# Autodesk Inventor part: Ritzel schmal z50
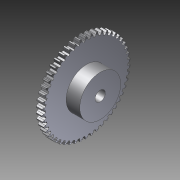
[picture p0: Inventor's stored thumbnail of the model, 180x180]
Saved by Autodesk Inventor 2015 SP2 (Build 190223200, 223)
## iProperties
Created: 2015-08
Part Number: Ritzel schmal z50
Material: Messing, weicher Gelbton
Document SubType Name: Modeling
Designer: ryll
Mass: 11.7013 g
Surface Area: 14.4914 cm^2
Volume: 1.3815 cm^3
Density: 8.47 g/cm^3
Appearance: Messing - satiniert
Title: c:/PPEXPORT/antriebselemente_und_normteile/stirnzahnraeder/stirnzahnraeder_messing/artikel_nr___26105000.stp
Creation Date: 2007-11-07
Author: ryll
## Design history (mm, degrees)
node "261050001"
node "1"
node "Basis1"
